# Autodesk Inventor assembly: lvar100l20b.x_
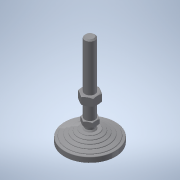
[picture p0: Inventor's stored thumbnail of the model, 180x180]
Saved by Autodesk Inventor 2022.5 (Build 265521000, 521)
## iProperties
Part Number: lvar100l20b.x_
Material: 一般
Document SubType Name: Assembly
Designer: ImaoCorp
Sending System: SOLIDWORKS 2017-2017317
MC: AMD64
MC_MODEL: Intel64 Family 6 Model 60 Stepping 3, GenuineIntel
OS: Windows_NT
FRU: Parasolid Version 29.0, build 201,  4-17-2017
FORMAT: text
GUISE: transmit
KEY: lvar100l20b
FILE: lvar100l20b.x_t
DATE: Mon Jul 01 18:10:33 2019
Author: ImaoCorp
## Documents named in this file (3)
- X:\14_SW2022-Inv2022\00_全2023-1023新製品(TCC)まで\l\lvar100l20b\LVAR100L20B.iam
- X:\14_SW2022-Inv2022\00_全2023-1023新製品(TCC)まで\l\lvar100l20b\lvar100l20b_01.ipt
- X:\14_SW2022-Inv2022\00_全2023-1023新製品(TCC)まで\l\lvar100l20b\lvar100l20b_02.ipt
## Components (2 placed, 2 different names)
1. lvar100l20b_01
2. lvar100l20b_02
